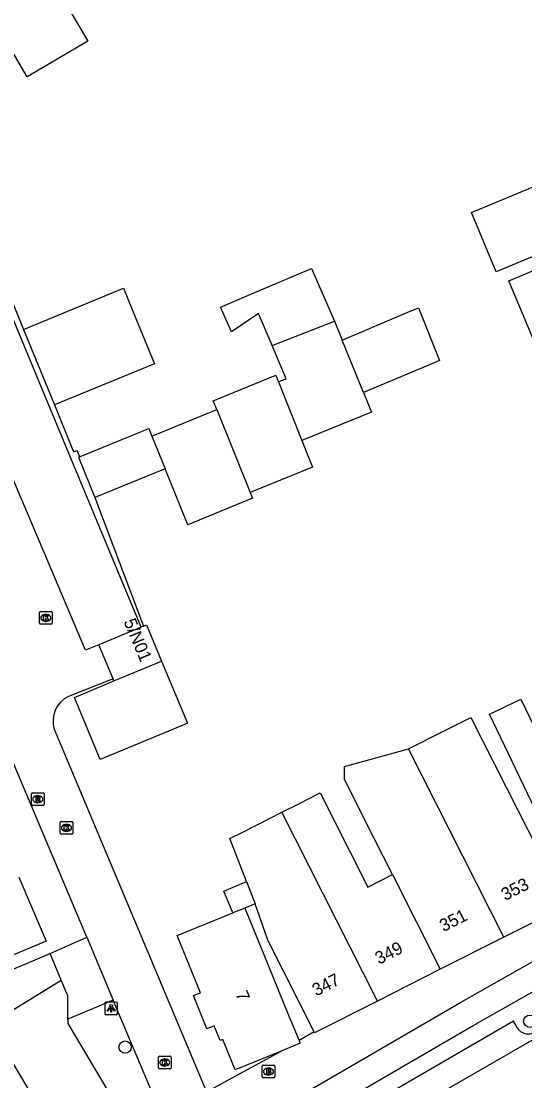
# Model space of a CAD drawing. Extents: x 163010 to 163853, y 382793 to 383982.
# Drawn here: x 163456.4 to 163496.4, y 383699.9 to 383784.1 of the extents above; entities that cross this region are included whole.
import ezdxf

# ---------------------------------------------------------------- set-up
doc = ezdxf.new("R2010")
doc.units = 0
for name, color, linetype in [('IMGEO_Boom', 7, 'Continuous'), ('IMGEO_Brandkraan', 7, 'Continuous'), ('IMGEO_Fietspad_open', 7, 'Continuous'), ('IMGEO_Groenvoorziening', 7, 'Continuous'), ('IMGEO_Kolk', 7, 'Continuous'), ('IMGEO_Lichtpunt', 7, 'Continuous'), ('IMGEO_Pand', 7, 'Continuous'), ('IMGEO_Pand_nummerreeks', 7, 'Continuous'), ('IMGEO_Parkeervlak_open', 7, 'Continuous'), ('IMGEO_Rijbaan_lokaal_gesloten', 7, 'Continuous'), ('IMGEO_Rijbaan_lokaal_open', 7, 'Continuous'), ('IMGEO_Rioolput', 7, 'Continuous'), ('IMGEO_Voetpad_open', 7, 'Continuous')]:
    doc.layers.add(name, color=color, linetype=linetype)

msp = doc.modelspace()

# ---------------------------------------------------------------- linework, layer by layer
at = {"layer": 'IMGEO_Boom'}
for centre in [(163496.816, 383704.614), (163464.657, 383702.557)]:
    msp.add_circle(centre, 0.489, dxfattribs=at)
at = {"layer": 'IMGEO_Brandkraan'}
for p, q in [((163475.55, 383700.183), (163475.55, 383701.035)), ((163475.625, 383701.109), (163476.477, 383701.109)), ((163476.038, 383700.889), (163476.063, 383700.889)), ((163476.551, 383701.035), (163476.551, 383700.183)), ((163476.477, 383700.109), (163475.625, 383700.109)), ((163476.061, 383700.329), (163476.036, 383700.329))]:
    msp.add_line(p, q, dxfattribs=at)
for points in [[(163475.55, 383700.183), (163475.55, 383701.035)], [(163475.625, 383701.109), (163476.477, 383701.109)], [(163475.898, 383700.809), (163475.898, 383700.409), (163476.111, 383700.409)], [(163476.129, 383700.809), (163475.898, 383700.809)], [(163476.077, 383700.728), (163476.023, 383700.728), (163476.023, 383700.652)], [(163476.023, 383700.652), (163476.076, 383700.652)], [(163476.551, 383701.035), (163476.551, 383700.183)], [(163476.477, 383700.109), (163475.625, 383700.109)], [(163476.085, 383700.576), (163476.023, 383700.576), (163476.023, 383700.495)], [(163476.023, 383700.495), (163476.085, 383700.495)]]:
    msp.add_lwpolyline(points, dxfattribs=at)
for centre, radius, start, end in [((163475.627, 383701.033), 0.0765, 91.55205, 178.44795), ((163475.627, 383701.033), 0.0765, 91.55205, 178.44795), ((163476.078, 383700.69), 0.0379, 267.82845, 90.93552), ((163476.133, 383700.664), 0.145, 59.4692, 91.53667), ((163476.158, 383700.711), 0.0922, 285.51372, 58.15012), ((163476.163, 383700.519), 0.105, 301.31148, 78.98903), ((163476.475, 383701.033), 0.0765, 1.55205, 88.44795), ((163476.475, 383701.033), 0.0765, 1.55205, 88.44795), ((163475.627, 383700.185), 0.0765, 181.55205, 268.44795), ((163475.627, 383700.185), 0.0765, 181.55205, 268.44795), ((163476.086, 383700.535), 0.0404, 269.87594, 90.50774), ((163476.117, 383700.66), 0.251, 268.66757, 293.53466), ((163476.475, 383700.185), 0.0765, 271.55205, 358.44795), ((163476.475, 383700.185), 0.0765, 271.55205, 358.44795)]:
    msp.add_arc(centre, radius, start, end, dxfattribs=at)
for centre, major_axis, ratio, start_param, end_param in [((163476.037, 383700.609), (-0.387, 0.002), 0.722429, 4.712389, 7.853982), ((163476.062, 383700.609), (-0.39, 0.002), 0.717154, 1.570796, 4.712389)]:
    msp.add_ellipse(centre, major_axis=major_axis, ratio=ratio, start_param=start_param, end_param=end_param, dxfattribs=at)
at = {"layer": 'IMGEO_Fietspad_open'}
for points in [[(163405.856, 383656.462), (163491.247, 383706.08), (163500, 383711.017), (163512.387, 383717.643), (163569.257, 383747.053), (163574.956, 383750), (163654.435, 383791.132)], [(163420.325, 383662.389), (163492.316, 383704.277), (163500, 383708.628), (163513.275, 383715.72), (163519.272, 383718.8), (163525.007, 383721.799)]]:
    msp.add_lwpolyline(points, dxfattribs=at)
at = {"layer": 'IMGEO_Groenvoorziening'}
for points in [[(163453.445, 383764.041), (163454.566, 383764.487), (163456.574, 383759.597)], [(163459.039, 383753.593), (163460.513, 383750), (163460.573, 383749.863), (163460.841, 383749.974), (163460.885, 383749.858), (163461.029, 383749.478)], [(163462.26, 383746.244), (163466.131, 383736.012)]]:
    msp.add_lwpolyline(points, dxfattribs=at)
at = {"layer": 'IMGEO_Kolk'}
for p, q in [((163457.855, 383736.239), (163457.855, 383737.091)), ((163457.93, 383737.165), (163458.782, 383737.165)), ((163458.343, 383736.945), (163458.368, 383736.945)), ((163458.856, 383737.091), (163458.856, 383736.239)), ((163458.782, 383736.165), (163457.93, 383736.165)), ((163458.366, 383736.385), (163458.341, 383736.385)), ((163459.495, 383719.547), (163459.495, 383720.399)), ((163459.57, 383720.473), (163460.422, 383720.473)), ((163459.983, 383720.253), (163460.008, 383720.253)), ((163460.496, 383720.399), (163460.496, 383719.547)), ((163460.422, 383719.473), (163459.57, 383719.473)), ((163460.006, 383719.693), (163459.981, 383719.693)), ((163467.307, 383700.905), (163467.307, 383701.757)), ((163467.382, 383701.831), (163468.234, 383701.831)), ((163467.795, 383701.611), (163467.82, 383701.611)), ((163468.308, 383701.757), (163468.308, 383700.905)), ((163468.234, 383700.831), (163467.382, 383700.831)), ((163467.818, 383701.051), (163467.793, 383701.051))]:
    msp.add_line(p, q, dxfattribs=at)
for points in [[(163457.855, 383736.239), (163457.855, 383737.091)], [(163457.93, 383737.165), (163458.782, 383737.165)], [(163458.176, 383736.865), (163458.299, 383736.865), (163458.299, 383736.714), (163458.429, 383736.865), (163458.593, 383736.865), (163458.447, 383736.714), (163458.6, 383736.465), (163458.448, 383736.465), (163458.363, 383736.629), (163458.299, 383736.562), (163458.299, 383736.465), (163458.176, 383736.465), (163458.176, 383736.865)], [(163458.856, 383737.091), (163458.856, 383736.239)], [(163458.782, 383736.165), (163457.93, 383736.165)], [(163459.495, 383719.547), (163459.495, 383720.399)], [(163459.57, 383720.473), (163460.422, 383720.473)], [(163459.816, 383720.173), (163459.939, 383720.173), (163459.939, 383720.022), (163460.069, 383720.173), (163460.233, 383720.173), (163460.087, 383720.022), (163460.24, 383719.773), (163460.088, 383719.773), (163460.003, 383719.937), (163459.939, 383719.87), (163459.939, 383719.773), (163459.816, 383719.773), (163459.816, 383720.173)], [(163460.496, 383720.399), (163460.496, 383719.547)], [(163460.422, 383719.473), (163459.57, 383719.473)], [(163467.307, 383700.905), (163467.307, 383701.757)], [(163467.382, 383701.831), (163468.234, 383701.831)], [(163467.628, 383701.531), (163467.751, 383701.531), (163467.751, 383701.38), (163467.881, 383701.531), (163468.045, 383701.531), (163467.899, 383701.38), (163468.052, 383701.131), (163467.9, 383701.131), (163467.815, 383701.295), (163467.751, 383701.228), (163467.751, 383701.131), (163467.628, 383701.131), (163467.628, 383701.531)], [(163468.308, 383701.757), (163468.308, 383700.905)], [(163468.234, 383700.831), (163467.382, 383700.831)]]:
    msp.add_lwpolyline(points, dxfattribs=at)
for centre, start, end in [((163457.932, 383737.089), 91.55205, 178.44795), ((163457.932, 383737.089), 91.55205, 178.44795), ((163458.78, 383737.089), 1.55205, 88.44795), ((163458.78, 383737.089), 1.55205, 88.44795), ((163457.932, 383736.241), 181.55205, 268.44795), ((163457.932, 383736.241), 181.55205, 268.44795), ((163458.78, 383736.241), 271.55205, 358.44795), ((163458.78, 383736.241), 271.55205, 358.44795), ((163459.572, 383720.397), 91.55205, 178.44795), ((163459.572, 383720.397), 91.55205, 178.44795), ((163460.42, 383720.397), 1.55205, 88.44795), ((163460.42, 383720.397), 1.55205, 88.44795), ((163459.572, 383719.549), 181.55205, 268.44795), ((163459.572, 383719.549), 181.55205, 268.44795), ((163460.42, 383719.549), 271.55205, 358.44795), ((163460.42, 383719.549), 271.55205, 358.44795), ((163467.384, 383701.755), 91.55205, 178.44795), ((163467.384, 383701.755), 91.55205, 178.44795), ((163468.232, 383701.755), 1.55205, 88.44795), ((163468.232, 383701.755), 1.55205, 88.44795), ((163467.384, 383700.907), 181.55205, 268.44795), ((163467.384, 383700.907), 181.55205, 268.44795), ((163468.232, 383700.907), 271.55205, 358.44795), ((163468.232, 383700.907), 271.55205, 358.44795)]:
    msp.add_arc(centre, 0.0765, start, end, dxfattribs=at)
for centre, major_axis, ratio, start_param, end_param in [((163458.342, 383736.665), (-0.387, 0.002), 0.722429, 4.712389, 7.853982), ((163458.367, 383736.665), (-0.39, 0.002), 0.717154, 1.570796, 4.712389), ((163459.982, 383719.973), (-0.387, 0.002), 0.722429, 4.712389, 7.853982), ((163460.007, 383719.973), (-0.39, 0.002), 0.717154, 1.570796, 4.712389), ((163467.794, 383701.331), (-0.387, 0.002), 0.722429, 4.712389, 7.853982), ((163467.819, 383701.331), (-0.39, 0.002), 0.717154, 1.570796, 4.712389)]:
    msp.add_ellipse(centre, major_axis=major_axis, ratio=ratio, start_param=start_param, end_param=end_param, dxfattribs=at)
at = {"layer": 'IMGEO_Lichtpunt'}
for p, q in [((163463.053, 383706.033), (163463.053, 383705.226)), ((163463.053, 383706.033), (163463.053, 383705.226)), ((163463.955, 383706.128), (163463.147, 383706.128)), ((163463.955, 383706.128), (163463.147, 383706.128)), ((163464.049, 383705.226), (163464.049, 383706.033)), ((163464.049, 383705.226), (163464.049, 383706.033)), ((163463.147, 383705.132), (163463.955, 383705.132)), ((163463.147, 383705.132), (163463.955, 383705.132))]:
    msp.add_line(p, q, dxfattribs=at)
for points in [[(163463.427, 383705.697), (163463.466, 383705.669), (163463.278, 383705.407), (163463.24, 383705.434), (163463.427, 383705.697)], [(163463.639, 383705.669), (163463.677, 383705.696), (163463.864, 383705.434), (163463.825, 383705.406), (163463.639, 383705.669)], [(163463.529, 383705.649), (163463.576, 383705.649), (163463.576, 383705.327), (163463.529, 383705.327), (163463.529, 383705.649)]]:
    msp.add_lwpolyline(points, dxfattribs=at)
msp.add_circle((163463.552, 383705.831), 0.0994, dxfattribs=at)
for centre, start, end in [((163463.147, 383706.033), 90, 180), ((163463.147, 383706.033), 90, 180), ((163463.955, 383706.033), 0, 90), ((163463.955, 383706.033), 0, 90), ((163463.147, 383705.226), 180, 270), ((163463.147, 383705.226), 180, 270), ((163463.955, 383705.226), 270, 0), ((163463.955, 383705.226), 270, 360)]:
    msp.add_arc(centre, 0.0946, start, end, dxfattribs=at)
at = {"layer": 'IMGEO_Pand'}
for points in [[(163461.702, 383782.503), (163456.863, 383779.658), (163453.639, 383785.143), (163458.478, 383787.987), (163461.702, 383782.503)], [(163494.147, 383764.168), (163492.179, 383768.873), (163498.671, 383771.588), (163500.639, 383766.883), (163494.147, 383764.168)], [(163503, 383758.138), (163498.214, 383756.137), (163496.715, 383759.721), (163495.154, 383763.454), (163499.939, 383765.456), (163502.573, 383759.158), (163503, 383758.138)], [(163476.333, 383758.323), (163475.249, 383760.868), (163473.116, 383759.391), (163472.248, 383761.36), (163474.837, 383762.482), (163479.468, 383764.431), (163481.295, 383760.24)], [(163456.574, 383759.597), (163464.529, 383762.864), (163465.514, 383760.466), (163466.995, 383756.859), (163459.039, 383753.593)], [(163481.901, 383758.751), (163487.111, 383760.957), (163487.45, 383761.101), (163487.962, 383761.318), (163489.644, 383757.134), (163489.208, 383756.949), (163483.602, 383754.574)], [(163456.574, 383759.597), (163457.558, 383757.2), (163459.039, 383753.593)], [(163476.333, 383758.323), (163481.295, 383760.24)], [(163481.295, 383760.24), (163481.901, 383758.751)], [(163483.602, 383754.574), (163481.901, 383758.751)], [(163476.833, 383755.423), (163477.212, 383755.577), (163477.46, 383755.678), (163476.333, 383758.323)], [(163471.937, 383753.219), (163471.652, 383753.918), (163476.625, 383755.943), (163476.833, 383755.423)], [(163476.833, 383755.423), (163478.705, 383750.753)], [(163483.602, 383754.574), (163484.24, 383753.007), (163478.705, 383750.753)], [(163466.776, 383751.117), (163471.937, 383753.219)], [(163471.937, 383753.219), (163474.597, 383746.632)], [(163461.029, 383749.478), (163466.531, 383751.719), (163466.776, 383751.117)], [(163466.776, 383751.117), (163467.836, 383748.515)], [(163478.705, 383750.753), (163479.549, 383748.648), (163474.597, 383746.632)], [(163461.029, 383749.478), (163460.955, 383749.448), (163462.26, 383746.244)], [(163467.836, 383748.515), (163462.26, 383746.244)], [(163474.597, 383746.632), (163474.786, 383746.168), (163469.645, 383744.074), (163467.836, 383748.515)], [(163466.131, 383736.012), (163465.925, 383735.926)], [(163466.131, 383736.012), (163466.359, 383736.107), (163467.556, 383733.227)], [(163465.925, 383735.926), (163462.572, 383734.532)], [(163463.704, 383731.812), (163462.572, 383734.532)], [(163467.556, 383733.227), (163469.62, 383728.292), (163469.186, 383728.112), (163462.685, 383725.408), (163460.631, 383730.348), (163463.77, 383731.653)], [(163463.77, 383731.653), (163467.556, 383733.227)], [(163463.77, 383731.653), (163463.704, 383731.812)], [(163500.716, 383714.236), (163500, 383715.726), (163498.55, 383718.742), (163497.254, 383721.433), (163493.613, 383729.003), (163496.109, 383730.204), (163499.75, 383722.635), (163500, 383722.755), (163503.014, 383724.205), (163503.242, 383724.315)], [(163487.183, 383726.261), (163489.851, 383727.609), (163492.134, 383728.762), (163495.889, 383721.331), (163497.447, 383718.248), (163499.701, 383713.785)], [(163485.901, 383716.265), (163484.419, 383719.198), (163482.08, 383723.827), (163482.104, 383724.842), (163487.183, 383726.261)], [(163494.748, 383711.283), (163487.183, 383726.261)], [(163477.114, 383721.219), (163478.462, 383721.9), (163480.166, 383722.761), (163482.465, 383718.21), (163483.946, 383715.278), (163485.901, 383716.265)], [(163474.299, 383715.711), (163472.986, 383719.133), (163473.999, 383719.645), (163477.114, 383721.219)], [(163484.703, 383706.208), (163477.114, 383721.219)], [(163456.223, 383716.054), (163458.371, 383710.975), (163453.758, 383709.047), (163450.676, 383707.773), (163448.996, 383711.778), (163446.138, 383710.583), (163446.626, 383709.415), (163444.234, 383708.415), (163443.164, 383710.532)], [(163485.901, 383716.265), (163489.705, 383708.735)], [(163473.222, 383713.222), (163472.498, 383714.959), (163474.299, 383715.711)], [(163474.299, 383715.711), (163474.981, 383713.933)], [(163474.175, 383713.607), (163473.222, 383713.222)], [(163474.981, 383713.933), (163474.175, 383713.607)], [(163474.175, 383713.607), (163475.684, 383709.912), (163477.574, 383705.282), (163478.476, 383703.08)], [(163479.672, 383703.755), (163475.988, 383711.048), (163474.981, 383713.933)], [(163499.701, 383713.785), (163494.748, 383711.283)], [(163477.064, 383702.243), (163473.403, 383700.745), (163472.41, 383703.169), (163472.203, 383703.084), (163471.735, 383704.237), (163471.16, 383704.004), (163470.086, 383706.649), (163470.644, 383706.876), (163468.802, 383711.434), (163473.222, 383713.222)], [(163494.748, 383711.283), (163489.705, 383708.735)], [(163446.777, 383704.826), (163447.787, 383705.429), (163454.082, 383708.07), (163458.694, 383709.998)], [(163459.583, 383707.87), (163458.694, 383709.998)], [(163489.705, 383708.735), (163484.703, 383706.208)], [(163461.143, 383692.244), (163454.999, 383702.541), (163454.556, 383703.283), (163454.482, 383703.407), (163455.163, 383703.796), (163455.507, 383705.364), (163459.583, 383707.87)], [(163460.096, 383704.778), (163460.103, 383706.627), (163459.583, 383707.87)], [(163484.703, 383706.208), (163479.708, 383703.684), (163479.672, 383703.755)], [(163460.096, 383704.778), (163460.095, 383704.42), (163465.729, 383694.981)], [(163478.476, 383703.08), (163478.499, 383703.025), (163478.567, 383702.858), (163477.064, 383702.243)]]:
    msp.add_lwpolyline(points, dxfattribs=at)
at = {"layer": 'IMGEO_Parkeervlak_open'}
for points in [[(163465.925, 383735.926), (163460.072, 383750), (163454.656, 383763.022), (163453.99, 383762.749)], [(163495.821, 383704.099), (163495.518, 383704.61), (163479.724, 383695.461)]]:
    msp.add_lwpolyline(points, dxfattribs=at)
msp.add_arc((163496.681, 383704.602), 0.996, 210.29864, 30.88907, dxfattribs=at)
at = {"layer": 'IMGEO_Rijbaan_lokaal_gesloten'}
msp.add_lwpolyline([(163596.899, 383755.251), (163586.731, 383750), (163571.98, 383742.358), (163507.275, 383708.837), (163500, 383704.831), (163477.846, 383692.06)], dxfattribs=at)
at = {"layer": 'IMGEO_Rijbaan_lokaal_open'}
for points in [[(163462.572, 383734.532), (163461.499, 383734.106), (163454.789, 383750), (163450.099, 383761.108)], [(163461.602, 383711.293), (163445.277, 383750), (163443.099, 383755.163)], [(163463.704, 383731.812), (163460.166, 383730.426)], [(163459.027, 383727.812), (163471.118, 383699.002)], [(163461.602, 383711.293), (163463.715, 383706.284)], [(163467.757, 383696.699), (163463.715, 383706.284)]]:
    msp.add_lwpolyline(points, dxfattribs=at)
msp.add_arc((163461.081, 383728.472), 2.157, 115.0854, 197.82613, dxfattribs=at)
at = {"layer": 'IMGEO_Rioolput'}
for p, q in [((163457.218, 383721.834), (163457.218, 383722.686)), ((163457.293, 383722.76), (163458.145, 383722.76)), ((163457.706, 383722.54), (163457.731, 383722.54)), ((163458.219, 383722.686), (163458.219, 383721.834)), ((163458.145, 383721.76), (163457.293, 383721.76)), ((163457.729, 383721.98), (163457.704, 383721.98))]:
    msp.add_line(p, q, dxfattribs=at)
for points in [[(163457.218, 383721.834), (163457.218, 383722.686)], [(163457.293, 383722.76), (163458.145, 383722.76)], [(163458.219, 383722.686), (163458.219, 383721.834)], [(163458.145, 383721.76), (163457.293, 383721.76)], [(163457.807, 383722.458), (163457.555, 383722.46), (163457.555, 383722.06)], [(163457.555, 383722.06), (163457.679, 383722.06), (163457.679, 383722.222), (163457.69, 383722.222)], [(163457.733, 383722.379), (163457.679, 383722.379), (163457.679, 383722.298)], [(163457.679, 383722.298), (163457.731, 383722.298)], [(163457.737, 383722.193), (163457.808, 383722.06), (163457.948, 383722.06), (163457.883, 383722.186)]]:
    msp.add_lwpolyline(points, dxfattribs=at)
for centre, radius, start, end in [((163457.295, 383722.684), 0.0765, 91.55205, 178.44795), ((163457.295, 383722.684), 0.0765, 91.55205, 178.44795), ((163458.143, 383722.684), 0.0765, 1.55205, 88.44795), ((163458.143, 383722.684), 0.0765, 1.55205, 88.44795), ((163457.295, 383721.836), 0.0765, 181.55205, 268.44795), ((163457.295, 383721.836), 0.0765, 181.55205, 268.44795), ((163457.689, 383722.169), 0.0533, 26.02933, 88.69889), ((163457.715, 383722.487), 0.19, 274.7715, 282.96867), ((163457.739, 383722.283), 0.0964, 77.00612, 93.18647), ((163457.753, 383722.34), 0.0378, 276.66336, 79.67722), ((163457.806, 383722.348), 0.109, 350.36119, 89.41601), ((163457.804, 383722.348), 0.112, 277.58423, 350.98172), ((163457.788, 383722.133), 0.108, 29.51342, 73.79051), ((163458.143, 383721.836), 0.0765, 271.55205, 358.44795), ((163458.143, 383721.836), 0.0765, 271.55205, 358.44795)]:
    msp.add_arc(centre, radius, start, end, dxfattribs=at)
for centre, major_axis, ratio, start_param, end_param in [((163457.705, 383722.26), (-0.387, 0.002), 0.722429, 4.712389, 7.853982), ((163457.73, 383722.26), (-0.39, 0.002), 0.717154, 1.570796, 4.712389)]:
    msp.add_ellipse(centre, major_axis=major_axis, ratio=ratio, start_param=start_param, end_param=end_param, dxfattribs=at)
at = {"layer": 'IMGEO_Voetpad_open'}
for points in [[(163458.694, 383709.998), (163461.602, 383711.293)], [(163463.715, 383706.284), (163460.096, 383704.778)], [(163479.672, 383703.755), (163478.476, 383703.08)], [(163471.118, 383699.002), (163477.064, 383702.243)]]:
    msp.add_lwpolyline(points, dxfattribs=at)

# ---------------------------------------------------------------- texts
at = {"layer": 'IMGEO_Pand_nummerreeks'}
for s, rotation, p in [('5/N01', 292.74156, (163464.52, 383736.373)), ('353', 26.80297, (163494.858, 383714.161)), ('351', 26.80297, (163489.961, 383711.687)), ('349', 26.80297, (163484.837, 383709.099)), ('347', 26.8087, (163479.839, 383706.573)), ('7', 292.47119, (163473.409, 383706.784))]:
    msp.add_text(s, height=1, rotation=rotation, dxfattribs=at).set_placement(p)

doc.saveas('drawing.dxf')
